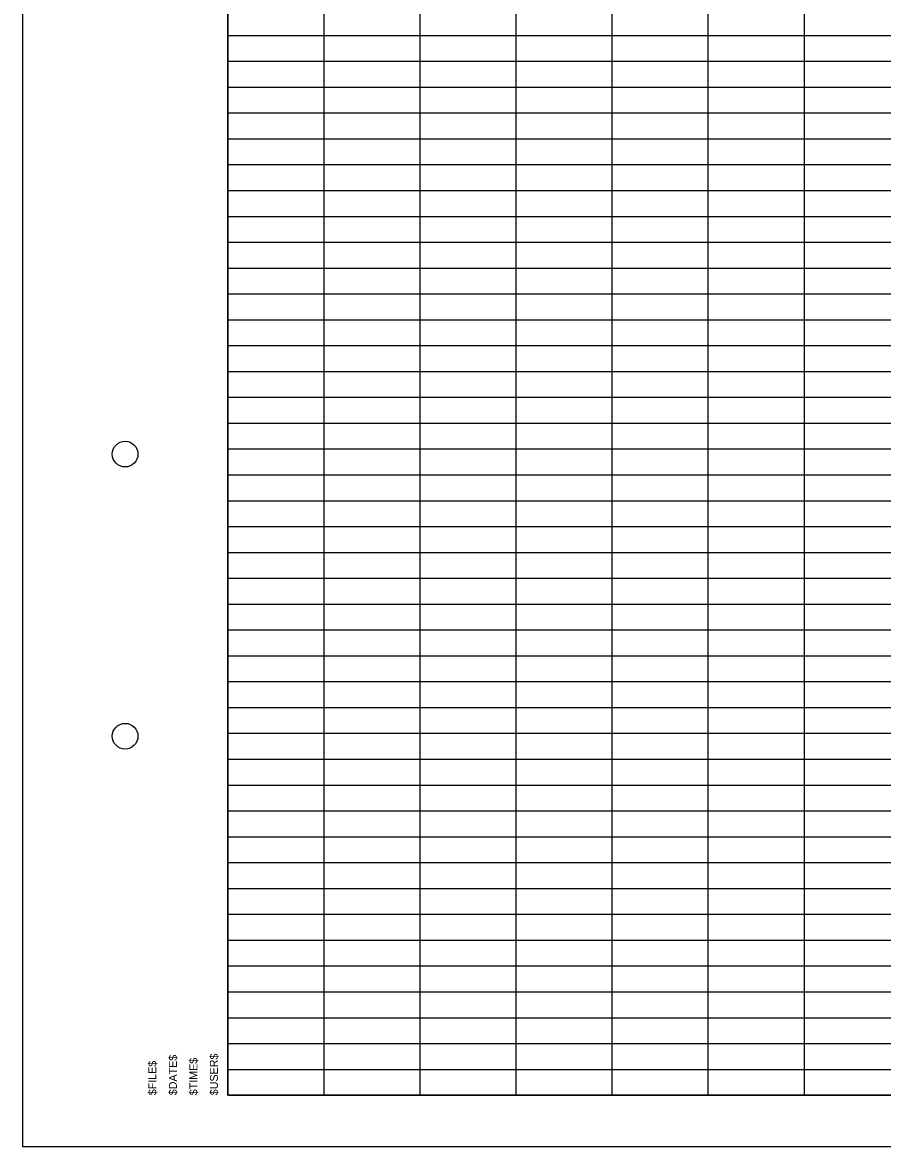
# Model space of a CAD drawing. Extents: x 1826847 to 2221677, y 500657 to 714743.
# Drawn here: x 1826847 to 1827266, y 713643 to 714191 of the extents above; entities that cross this region are included whole.
import ezdxf

# ---------------------------------------------------------------- set-up
doc = ezdxf.new("R2010")
doc.units = 0
for name, color, linetype in [('SH_Border', 7, 'Continuous'), ('SH_Cut_Line', 7, 'Continuous'), ('SH_Data', 7, 'Continuous'), ('TX_P_Misc', 7, 'Continuous')]:
    doc.layers.add(name, color=color, linetype=linetype)

msp = doc.modelspace()

# ---------------------------------------------------------------- linework, layer by layer
at = {"layer": 'SH_Border'}
msp.add_lwpolyline([(1826946.62, 714718.08), (1828521.62, 714718.08), (1828521.62, 713668.08), (1826946.62, 713668.08)], close=True, dxfattribs=at)
for centre in [(1826896.62, 713980.58), (1826896.62, 713843.08)]:
    msp.add_circle(centre, 6.25, dxfattribs=at)
at = {"layer": 'SH_Cut_Line'}
msp.add_lwpolyline([(1826846.62, 713643.08), (1828546.62, 713643.08), (1828546.62, 714743.08), (1826846.62, 714743.08)], close=True, dxfattribs=at)
at = {"layer": 'SH_Data'}
for p, q in [((1826946.62, 714222.48), (1826946.62, 714159.48)), ((1826993.42, 714222.48), (1826993.42, 714159.48)), ((1827040.22, 714222.48), (1827040.22, 714159.48)), ((1827087.02, 714222.48), (1827087.02, 714159.48)), ((1827133.82, 714222.48), (1827133.82, 714159.48)), ((1827180.62, 714222.48), (1827180.62, 714159.48)), ((1827227.42, 714222.48), (1827227.42, 714159.48)), ((1826946.62, 714184.68), (1826993.42, 714184.68)), ((1826993.42, 714184.68), (1827040.22, 714184.68)), ((1827040.22, 714184.68), (1827087.02, 714184.68)), ((1827087.02, 714184.68), (1827133.82, 714184.68)), ((1827133.82, 714184.68), (1827180.62, 714184.68)), ((1827180.62, 714184.68), (1827227.42, 714184.68)), ((1827227.42, 714184.68), (1827274.22, 714184.68)), ((1826946.62, 714172.08), (1826993.42, 714172.08)), ((1826993.42, 714172.08), (1827040.22, 714172.08)), ((1827040.22, 714172.08), (1827087.02, 714172.08)), ((1827087.02, 714172.08), (1827133.82, 714172.08)), ((1827133.82, 714172.08), (1827180.62, 714172.08)), ((1827180.62, 714172.08), (1827227.42, 714172.08)), ((1827227.42, 714172.08), (1827274.22, 714172.08)), ((1826946.62, 714159.48), (1826993.42, 714159.48)), ((1826946.62, 714159.48), (1826946.62, 714096.48)), ((1826993.42, 714159.48), (1827040.22, 714159.48)), ((1826993.42, 714159.48), (1826993.42, 714096.48)), ((1827040.22, 714159.48), (1827087.02, 714159.48)), ((1827040.22, 714159.48), (1827040.22, 714096.48)), ((1827087.02, 714159.48), (1827133.82, 714159.48)), ((1827087.02, 714159.48), (1827087.02, 714096.48)), ((1827133.82, 714159.48), (1827180.62, 714159.48)), ((1827133.82, 714159.48), (1827133.82, 714096.48)), ((1827180.62, 714159.48), (1827227.42, 714159.48)), ((1827180.62, 714159.48), (1827180.62, 714096.48)), ((1827227.42, 714159.48), (1827274.22, 714159.48)), ((1827227.42, 714159.48), (1827227.42, 714096.48)), ((1826946.62, 714146.88), (1826993.42, 714146.88)), ((1826993.42, 714146.88), (1827040.22, 714146.88)), ((1827040.22, 714146.88), (1827087.02, 714146.88)), ((1827087.02, 714146.88), (1827133.82, 714146.88)), ((1827133.82, 714146.88), (1827180.62, 714146.88)), ((1827180.62, 714146.88), (1827227.42, 714146.88)), ((1827227.42, 714146.88), (1827274.22, 714146.88)), ((1826946.62, 714134.28), (1826993.42, 714134.28)), ((1826993.42, 714134.28), (1827040.22, 714134.28)), ((1827040.22, 714134.28), (1827087.02, 714134.28)), ((1827087.02, 714134.28), (1827133.82, 714134.28)), ((1827133.82, 714134.28), (1827180.62, 714134.28)), ((1827180.62, 714134.28), (1827227.42, 714134.28)), ((1827227.42, 714134.28), (1827274.22, 714134.28)), ((1826946.62, 714121.68), (1826993.42, 714121.68)), ((1826993.42, 714121.68), (1827040.22, 714121.68)), ((1827040.22, 714121.68), (1827087.02, 714121.68)), ((1827087.02, 714121.68), (1827133.82, 714121.68)), ((1827133.82, 714121.68), (1827180.62, 714121.68)), ((1827180.62, 714121.68), (1827227.42, 714121.68)), ((1827227.42, 714121.68), (1827274.22, 714121.68)), ((1826946.62, 714109.08), (1826993.42, 714109.08)), ((1826993.42, 714109.08), (1827040.22, 714109.08)), ((1827040.22, 714109.08), (1827087.02, 714109.08)), ((1827087.02, 714109.08), (1827133.82, 714109.08)), ((1827133.82, 714109.08), (1827180.62, 714109.08)), ((1827180.62, 714109.08), (1827227.42, 714109.08)), ((1827227.42, 714109.08), (1827274.22, 714109.08)), ((1826946.62, 714096.48), (1826993.42, 714096.48)), ((1826946.62, 714096.48), (1826946.62, 714033.48)), ((1826993.42, 714096.48), (1827040.22, 714096.48)), ((1826993.42, 714096.48), (1826993.42, 714033.48)), ((1827040.22, 714096.48), (1827087.02, 714096.48)), ((1827040.22, 714096.48), (1827040.22, 714033.48)), ((1827087.02, 714096.48), (1827133.82, 714096.48)), ((1827087.02, 714096.48), (1827087.02, 714033.48)), ((1827133.82, 714096.48), (1827180.62, 714096.48)), ((1827133.82, 714096.48), (1827133.82, 714033.48)), ((1827180.62, 714096.48), (1827227.42, 714096.48)), ((1827180.62, 714096.48), (1827180.62, 714033.48)), ((1827227.42, 714096.48), (1827274.22, 714096.48)), ((1827227.42, 714096.48), (1827227.42, 714033.48)), ((1826946.62, 714083.88), (1826993.42, 714083.88)), ((1826993.42, 714083.88), (1827040.22, 714083.88)), ((1827040.22, 714083.88), (1827087.02, 714083.88)), ((1827087.02, 714083.88), (1827133.82, 714083.88)), ((1827133.82, 714083.88), (1827180.62, 714083.88)), ((1827180.62, 714083.88), (1827227.42, 714083.88)), ((1827227.42, 714083.88), (1827274.22, 714083.88)), ((1826946.62, 714071.28), (1826993.42, 714071.28)), ((1826993.42, 714071.28), (1827040.22, 714071.28)), ((1827040.22, 714071.28), (1827087.02, 714071.28)), ((1827087.02, 714071.28), (1827133.82, 714071.28)), ((1827133.82, 714071.28), (1827180.62, 714071.28)), ((1827180.62, 714071.28), (1827227.42, 714071.28)), ((1827227.42, 714071.28), (1827274.22, 714071.28)), ((1826946.62, 714058.68), (1826993.42, 714058.68)), ((1826993.42, 714058.68), (1827040.22, 714058.68)), ((1827040.22, 714058.68), (1827087.02, 714058.68)), ((1827087.02, 714058.68), (1827133.82, 714058.68)), ((1827133.82, 714058.68), (1827180.62, 714058.68)), ((1827180.62, 714058.68), (1827227.42, 714058.68)), ((1827227.42, 714058.68), (1827274.22, 714058.68)), ((1826946.62, 714046.08), (1826993.42, 714046.08)), ((1826993.42, 714046.08), (1827040.22, 714046.08)), ((1827040.22, 714046.08), (1827087.02, 714046.08)), ((1827087.02, 714046.08), (1827133.82, 714046.08)), ((1827133.82, 714046.08), (1827180.62, 714046.08)), ((1827180.62, 714046.08), (1827227.42, 714046.08)), ((1827227.42, 714046.08), (1827274.22, 714046.08)), ((1826946.62, 714033.48), (1826993.42, 714033.48)), ((1826946.62, 714033.48), (1826946.62, 713970.48)), ((1826993.42, 714033.48), (1827040.22, 714033.48)), ((1826993.42, 714033.48), (1826993.42, 713970.48)), ((1827040.22, 714033.48), (1827087.02, 714033.48)), ((1827040.22, 714033.48), (1827040.22, 713970.48)), ((1827087.02, 714033.48), (1827133.82, 714033.48)), ((1827087.02, 714033.48), (1827087.02, 713970.48)), ((1827133.82, 714033.48), (1827180.62, 714033.48)), ((1827133.82, 714033.48), (1827133.82, 713970.48)), ((1827180.62, 714033.48), (1827227.42, 714033.48)), ((1827180.62, 714033.48), (1827180.62, 713970.48)), ((1827227.42, 714033.48), (1827274.22, 714033.48)), ((1827227.42, 714033.48), (1827227.42, 713970.48)), ((1826946.62, 714020.88), (1826993.42, 714020.88)), ((1826993.42, 714020.88), (1827040.22, 714020.88)), ((1827040.22, 714020.88), (1827087.02, 714020.88)), ((1827087.02, 714020.88), (1827133.82, 714020.88)), ((1827133.82, 714020.88), (1827180.62, 714020.88)), ((1827180.62, 714020.88), (1827227.42, 714020.88)), ((1827227.42, 714020.88), (1827274.22, 714020.88)), ((1826946.62, 714008.28), (1826993.42, 714008.28)), ((1826993.42, 714008.28), (1827040.22, 714008.28)), ((1827040.22, 714008.28), (1827087.02, 714008.28)), ((1827087.02, 714008.28), (1827133.82, 714008.28)), ((1827133.82, 714008.28), (1827180.62, 714008.28)), ((1827180.62, 714008.28), (1827227.42, 714008.28)), ((1827227.42, 714008.28), (1827274.22, 714008.28)), ((1826946.62, 713995.68), (1826993.42, 713995.68)), ((1826993.42, 713995.68), (1827040.22, 713995.68)), ((1827040.22, 713995.68), (1827087.02, 713995.68)), ((1827087.02, 713995.68), (1827133.82, 713995.68)), ((1827133.82, 713995.68), (1827180.62, 713995.68)), ((1827180.62, 713995.68), (1827227.42, 713995.68)), ((1827227.42, 713995.68), (1827274.22, 713995.68)), ((1826946.62, 713983.08), (1826993.42, 713983.08)), ((1826993.42, 713983.08), (1827040.22, 713983.08)), ((1827040.22, 713983.08), (1827087.02, 713983.08)), ((1827087.02, 713983.08), (1827133.82, 713983.08)), ((1827133.82, 713983.08), (1827180.62, 713983.08)), ((1827180.62, 713983.08), (1827227.42, 713983.08)), ((1827227.42, 713983.08), (1827274.22, 713983.08)), ((1826946.62, 713970.48), (1826993.42, 713970.48)), ((1826946.62, 713970.48), (1826946.62, 713907.48)), ((1826993.42, 713970.48), (1827040.22, 713970.48)), ((1826993.42, 713970.48), (1826993.42, 713907.48)), ((1827040.22, 713970.48), (1827087.02, 713970.48)), ((1827040.22, 713970.48), (1827040.22, 713907.48)), ((1827087.02, 713970.48), (1827133.82, 713970.48)), ((1827087.02, 713970.48), (1827087.02, 713907.48)), ((1827133.82, 713970.48), (1827180.62, 713970.48)), ((1827133.82, 713970.48), (1827133.82, 713907.48)), ((1827180.62, 713970.48), (1827227.42, 713970.48)), ((1827180.62, 713970.48), (1827180.62, 713907.48)), ((1827227.42, 713970.48), (1827274.22, 713970.48)), ((1827227.42, 713970.48), (1827227.42, 713907.48)), ((1826946.62, 713957.88), (1826993.42, 713957.88)), ((1826993.42, 713957.88), (1827040.22, 713957.88)), ((1827040.22, 713957.88), (1827087.02, 713957.88)), ((1827087.02, 713957.88), (1827133.82, 713957.88)), ((1827133.82, 713957.88), (1827180.62, 713957.88)), ((1827180.62, 713957.88), (1827227.42, 713957.88)), ((1827227.42, 713957.88), (1827274.22, 713957.88)), ((1826946.62, 713945.28), (1826993.42, 713945.28)), ((1826993.42, 713945.28), (1827040.22, 713945.28)), ((1827040.22, 713945.28), (1827087.02, 713945.28)), ((1827087.02, 713945.28), (1827133.82, 713945.28)), ((1827133.82, 713945.28), (1827180.62, 713945.28)), ((1827180.62, 713945.28), (1827227.42, 713945.28)), ((1827227.42, 713945.28), (1827274.22, 713945.28)), ((1826946.62, 713932.68), (1826993.42, 713932.68)), ((1826993.42, 713932.68), (1827040.22, 713932.68)), ((1827040.22, 713932.68), (1827087.02, 713932.68)), ((1827087.02, 713932.68), (1827133.82, 713932.68)), ((1827133.82, 713932.68), (1827180.62, 713932.68)), ((1827180.62, 713932.68), (1827227.42, 713932.68)), ((1827227.42, 713932.68), (1827274.22, 713932.68)), ((1826946.62, 713920.08), (1826993.42, 713920.08)), ((1826993.42, 713920.08), (1827040.22, 713920.08)), ((1827040.22, 713920.08), (1827087.02, 713920.08)), ((1827087.02, 713920.08), (1827133.82, 713920.08)), ((1827133.82, 713920.08), (1827180.62, 713920.08)), ((1827180.62, 713920.08), (1827227.42, 713920.08)), ((1827227.42, 713920.08), (1827274.22, 713920.08)), ((1826946.62, 713907.48), (1826993.42, 713907.48)), ((1826946.62, 713907.48), (1826946.62, 713844.48)), ((1826993.42, 713907.48), (1827040.22, 713907.48)), ((1826993.42, 713907.48), (1826993.42, 713844.48)), ((1827040.22, 713907.48), (1827087.02, 713907.48)), ((1827040.22, 713907.48), (1827040.22, 713844.48)), ((1827087.02, 713907.48), (1827133.82, 713907.48)), ((1827087.02, 713907.48), (1827087.02, 713844.48)), ((1827133.82, 713907.48), (1827180.62, 713907.48)), ((1827133.82, 713907.48), (1827133.82, 713844.48)), ((1827180.62, 713907.48), (1827227.42, 713907.48)), ((1827180.62, 713907.48), (1827180.62, 713844.48)), ((1827227.42, 713907.48), (1827274.22, 713907.48)), ((1827227.42, 713907.48), (1827227.42, 713844.48)), ((1826946.62, 713894.88), (1826993.42, 713894.88)), ((1826993.42, 713894.88), (1827040.22, 713894.88)), ((1827040.22, 713894.88), (1827087.02, 713894.88)), ((1827087.02, 713894.88), (1827133.82, 713894.88)), ((1827133.82, 713894.88), (1827180.62, 713894.88)), ((1827180.62, 713894.88), (1827227.42, 713894.88)), ((1827227.42, 713894.88), (1827274.22, 713894.88)), ((1826946.62, 713882.28), (1826993.42, 713882.28)), ((1826993.42, 713882.28), (1827040.22, 713882.28)), ((1827040.22, 713882.28), (1827087.02, 713882.28)), ((1827087.02, 713882.28), (1827133.82, 713882.28)), ((1827133.82, 713882.28), (1827180.62, 713882.28)), ((1827180.62, 713882.28), (1827227.42, 713882.28)), ((1827227.42, 713882.28), (1827274.22, 713882.28)), ((1826946.62, 713869.68), (1826993.42, 713869.68)), ((1826993.42, 713869.68), (1827040.22, 713869.68)), ((1827040.22, 713869.68), (1827087.02, 713869.68)), ((1827087.02, 713869.68), (1827133.82, 713869.68)), ((1827133.82, 713869.68), (1827180.62, 713869.68)), ((1827180.62, 713869.68), (1827227.42, 713869.68)), ((1827227.42, 713869.68), (1827274.22, 713869.68)), ((1826946.62, 713857.08), (1826993.42, 713857.08)), ((1826993.42, 713857.08), (1827040.22, 713857.08)), ((1827040.22, 713857.08), (1827087.02, 713857.08)), ((1827087.02, 713857.08), (1827133.82, 713857.08)), ((1827133.82, 713857.08), (1827180.62, 713857.08)), ((1827180.62, 713857.08), (1827227.42, 713857.08)), ((1827227.42, 713857.08), (1827274.22, 713857.08)), ((1826946.62, 713844.48), (1826993.42, 713844.48)), ((1826946.62, 713844.48), (1826946.62, 713781.48)), ((1826993.42, 713844.48), (1827040.22, 713844.48)), ((1826993.42, 713844.48), (1826993.42, 713781.48)), ((1827040.22, 713844.48), (1827087.02, 713844.48)), ((1827040.22, 713844.48), (1827040.22, 713781.48)), ((1827087.02, 713844.48), (1827133.82, 713844.48)), ((1827087.02, 713844.48), (1827087.02, 713781.48)), ((1827133.82, 713844.48), (1827180.62, 713844.48)), ((1827133.82, 713844.48), (1827133.82, 713781.48)), ((1827180.62, 713844.48), (1827227.42, 713844.48)), ((1827180.62, 713844.48), (1827180.62, 713781.48)), ((1827227.42, 713844.48), (1827274.22, 713844.48)), ((1827227.42, 713844.48), (1827227.42, 713781.48)), ((1826946.62, 713831.88), (1826993.42, 713831.88)), ((1826993.42, 713831.88), (1827040.22, 713831.88)), ((1827040.22, 713831.88), (1827087.02, 713831.88)), ((1827087.02, 713831.88), (1827133.82, 713831.88)), ((1827133.82, 713831.88), (1827180.62, 713831.88)), ((1827180.62, 713831.88), (1827227.42, 713831.88)), ((1827227.42, 713831.88), (1827274.22, 713831.88)), ((1826946.62, 713819.28), (1826993.42, 713819.28)), ((1826993.42, 713819.28), (1827040.22, 713819.28)), ((1827040.22, 713819.28), (1827087.02, 713819.28)), ((1827087.02, 713819.28), (1827133.82, 713819.28)), ((1827133.82, 713819.28), (1827180.62, 713819.28)), ((1827180.62, 713819.28), (1827227.42, 713819.28)), ((1827227.42, 713819.28), (1827274.22, 713819.28)), ((1826946.62, 713806.68), (1826993.42, 713806.68)), ((1826993.42, 713806.68), (1827040.22, 713806.68)), ((1827040.22, 713806.68), (1827087.02, 713806.68)), ((1827087.02, 713806.68), (1827133.82, 713806.68)), ((1827133.82, 713806.68), (1827180.62, 713806.68)), ((1827180.62, 713806.68), (1827227.42, 713806.68)), ((1827227.42, 713806.68), (1827274.22, 713806.68)), ((1826946.62, 713794.08), (1826993.42, 713794.08)), ((1826993.42, 713794.08), (1827040.22, 713794.08)), ((1827040.22, 713794.08), (1827087.02, 713794.08)), ((1827087.02, 713794.08), (1827133.82, 713794.08)), ((1827133.82, 713794.08), (1827180.62, 713794.08)), ((1827180.62, 713794.08), (1827227.42, 713794.08)), ((1827227.42, 713794.08), (1827274.22, 713794.08)), ((1826946.62, 713781.48), (1826993.42, 713781.48)), ((1826946.62, 713781.48), (1826946.62, 713768.88)), ((1826993.42, 713781.48), (1827040.22, 713781.48)), ((1826993.42, 713781.48), (1826993.42, 713768.88)), ((1827040.22, 713781.48), (1827087.02, 713781.48)), ((1827040.22, 713781.48), (1827040.22, 713768.88)), ((1827087.02, 713781.48), (1827133.82, 713781.48)), ((1827087.02, 713781.48), (1827087.02, 713768.88)), ((1827133.82, 713781.48), (1827180.62, 713781.48)), ((1827133.82, 713781.48), (1827133.82, 713768.88)), ((1827180.62, 713781.48), (1827227.42, 713781.48)), ((1827180.62, 713781.48), (1827180.62, 713768.88)), ((1827227.42, 713781.48), (1827274.22, 713781.48)), ((1827227.42, 713781.48), (1827227.42, 713768.88)), ((1826946.62, 713768.88), (1826993.42, 713768.88)), ((1826946.62, 713768.88), (1826946.62, 713756.28)), ((1826993.42, 713768.88), (1827040.22, 713768.88)), ((1826993.42, 713768.88), (1826993.42, 713756.28)), ((1827040.22, 713768.88), (1827087.02, 713768.88)), ((1827040.22, 713768.88), (1827040.22, 713756.28)), ((1827087.02, 713768.88), (1827133.82, 713768.88)), ((1827087.02, 713768.88), (1827087.02, 713756.28)), ((1827133.82, 713768.88), (1827180.62, 713768.88)), ((1827133.82, 713768.88), (1827133.82, 713756.28)), ((1827180.62, 713768.88), (1827227.42, 713768.88)), ((1827180.62, 713768.88), (1827180.62, 713756.28)), ((1827227.42, 713768.88), (1827274.22, 713768.88)), ((1827227.42, 713768.88), (1827227.42, 713756.28)), ((1826946.62, 713756.28), (1826993.42, 713756.28)), ((1826946.62, 713756.28), (1826946.62, 713743.68)), ((1826993.42, 713756.28), (1827040.22, 713756.28)), ((1826993.42, 713756.28), (1826993.42, 713743.68)), ((1827040.22, 713756.28), (1827087.02, 713756.28)), ((1827040.22, 713756.28), (1827040.22, 713743.68)), ((1827087.02, 713756.28), (1827133.82, 713756.28)), ((1827087.02, 713756.28), (1827087.02, 713743.68)), ((1827133.82, 713756.28), (1827180.62, 713756.28)), ((1827133.82, 713756.28), (1827133.82, 713743.68)), ((1827180.62, 713756.28), (1827227.42, 713756.28)), ((1827180.62, 713756.28), (1827180.62, 713743.68)), ((1827227.42, 713756.28), (1827274.22, 713756.28)), ((1827227.42, 713756.28), (1827227.42, 713743.68)), ((1826946.62, 713743.68), (1826993.42, 713743.68)), ((1826946.62, 713743.68), (1826946.62, 713731.08)), ((1826993.42, 713743.68), (1827040.22, 713743.68)), ((1826993.42, 713743.68), (1826993.42, 713731.08)), ((1827040.22, 713743.68), (1827087.02, 713743.68)), ((1827040.22, 713743.68), (1827040.22, 713731.08)), ((1827087.02, 713743.68), (1827133.82, 713743.68)), ((1827087.02, 713743.68), (1827087.02, 713731.08)), ((1827133.82, 713743.68), (1827180.62, 713743.68)), ((1827133.82, 713743.68), (1827133.82, 713731.08)), ((1827180.62, 713743.68), (1827227.42, 713743.68)), ((1827180.62, 713743.68), (1827180.62, 713731.08)), ((1827227.42, 713743.68), (1827274.22, 713743.68)), ((1827227.42, 713743.68), (1827227.42, 713731.08)), ((1826946.62, 713731.08), (1826993.42, 713731.08)), ((1826946.62, 713731.08), (1826946.62, 713718.48)), ((1826993.42, 713731.08), (1827040.22, 713731.08)), ((1826993.42, 713731.08), (1826993.42, 713718.48)), ((1827040.22, 713731.08), (1827087.02, 713731.08)), ((1827040.22, 713731.08), (1827040.22, 713718.48)), ((1827087.02, 713731.08), (1827133.82, 713731.08)), ((1827087.02, 713731.08), (1827087.02, 713718.48)), ((1827133.82, 713731.08), (1827180.62, 713731.08)), ((1827133.82, 713731.08), (1827133.82, 713718.48)), ((1827180.62, 713731.08), (1827227.42, 713731.08)), ((1827180.62, 713731.08), (1827180.62, 713718.48)), ((1827227.42, 713731.08), (1827274.22, 713731.08)), ((1827227.42, 713731.08), (1827227.42, 713718.48)), ((1826946.62, 713718.48), (1826993.42, 713718.48)), ((1826946.62, 713718.48), (1826946.62, 713705.88)), ((1826993.42, 713718.48), (1827040.22, 713718.48)), ((1826993.42, 713718.48), (1826993.42, 713705.88)), ((1827040.22, 713718.48), (1827087.02, 713718.48)), ((1827040.22, 713718.48), (1827040.22, 713705.88)), ((1827087.02, 713718.48), (1827133.82, 713718.48)), ((1827087.02, 713718.48), (1827087.02, 713705.88)), ((1827133.82, 713718.48), (1827180.62, 713718.48)), ((1827133.82, 713718.48), (1827133.82, 713705.88)), ((1827180.62, 713718.48), (1827227.42, 713718.48)), ((1827180.62, 713718.48), (1827180.62, 713705.88)), ((1827227.42, 713718.48), (1827274.22, 713718.48)), ((1827227.42, 713718.48), (1827227.42, 713705.88)), ((1826946.62, 713705.88), (1826993.42, 713705.88)), ((1826946.62, 713705.88), (1826946.62, 713668.08)), ((1826993.42, 713705.88), (1827040.22, 713705.88)), ((1826993.42, 713705.88), (1826993.42, 713668.08)), ((1827040.22, 713705.88), (1827087.02, 713705.88)), ((1827040.22, 713705.88), (1827040.22, 713668.08)), ((1827087.02, 713705.88), (1827133.82, 713705.88)), ((1827087.02, 713705.88), (1827087.02, 713668.08)), ((1827133.82, 713705.88), (1827180.62, 713705.88)), ((1827133.82, 713705.88), (1827133.82, 713668.08)), ((1827180.62, 713705.88), (1827227.42, 713705.88)), ((1827180.62, 713705.88), (1827180.62, 713668.08)), ((1827227.42, 713705.88), (1827274.22, 713705.88)), ((1827227.42, 713705.88), (1827227.42, 713668.08)), ((1826946.62, 713693.28), (1826993.42, 713693.28)), ((1826993.42, 713693.28), (1827040.22, 713693.28)), ((1827040.22, 713693.28), (1827087.02, 713693.28)), ((1827087.02, 713693.28), (1827133.82, 713693.28)), ((1827133.82, 713693.28), (1827180.62, 713693.28)), ((1827180.62, 713693.28), (1827227.42, 713693.28)), ((1827227.42, 713693.28), (1827274.22, 713693.28)), ((1826946.62, 713680.68), (1826993.42, 713680.68)), ((1826993.42, 713680.68), (1827040.22, 713680.68)), ((1827040.22, 713680.68), (1827087.02, 713680.68)), ((1827087.02, 713680.68), (1827133.82, 713680.68)), ((1827133.82, 713680.68), (1827180.62, 713680.68)), ((1827180.62, 713680.68), (1827227.42, 713680.68)), ((1827227.42, 713680.68), (1827274.22, 713680.68)), ((1826946.62, 713668.08), (1826993.42, 713668.08)), ((1826993.42, 713668.08), (1827040.22, 713668.08)), ((1827040.22, 713668.08), (1827087.02, 713668.08)), ((1827087.02, 713668.08), (1827133.82, 713668.08)), ((1827133.82, 713668.08), (1827180.62, 713668.08)), ((1827180.62, 713668.08), (1827227.42, 713668.08)), ((1827227.42, 713668.08), (1827274.22, 713668.08))]:
    msp.add_line(p, q, dxfattribs=at)

# ---------------------------------------------------------------- texts
at = {"layer": 'TX_P_Misc'}
for s, p in [('$FILE$', (1826911.85, 713668.07)), ('$DATE$', (1826921.85, 713668.07)), ('$TIME$', (1826931.85, 713668.07)), ('$USER$', (1826941.85, 713668.07))]:
    msp.add_text(s, height=3.9, rotation=90, dxfattribs=at).set_placement(p)

doc.saveas('drawing.dxf')
